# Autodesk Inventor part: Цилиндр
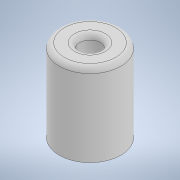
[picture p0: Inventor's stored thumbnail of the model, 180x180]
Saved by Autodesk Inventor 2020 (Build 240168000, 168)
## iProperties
Created: 2023-11
Part Number: Цилиндр
Material: Типовые
Document SubType Name: Modeling
Designer: User
Density: 1 g/cm^3
Appearance: По умолчанию
Author: User
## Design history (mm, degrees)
sketch "Эскиз1"
  geometry: C1 r 2 at (0, 0); C2 r 6 at (0, 0); 1 further point
  constraints: 3 coincident, 2 centre point
extrude "Выдавливание1" new body sketch "Эскиз1" distance "d2" = 16; taper "d3" = 0 deg
fillet "Сопряжение2" dims "d5" = 1
node "Твердое тело1"
